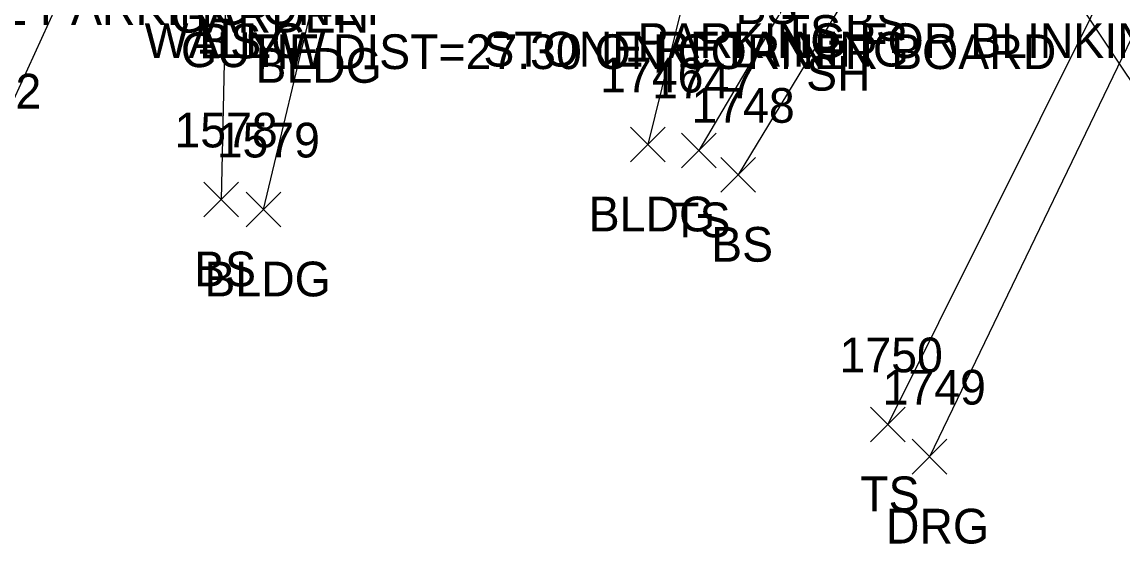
# Model space of a CAD drawing. Extents: x 1657482 to 1661439, y 647981 to 649041.
# Drawn here: x 1659845.2 to 1659908.5, y 648015.4 to 648045.5 of the extents above; entities that cross this region are included whole.
import ezdxf

# ---------------------------------------------------------------- set-up
doc = ezdxf.new("R2010")
doc.units = 0
for name, color, linetype in [('C_C', 7, 'Continuous'), ('DCP', 7, 'Continuous'), ('L_A', 7, 'Continuous'), ('L_C', 7, 'Continuous'), ('L_I', 7, 'Continuous'), ('L_TIC', 7, 'Continuous'), ('LBC', 7, 'Continuous'), ('LELB', 7, 'Continuous'), ('R_A', 7, 'Continuous'), ('R_I', 7, 'Continuous'), ('R_TIC', 7, 'Continuous'), ('RDG', 7, 'Continuous'), ('S_C', 7, 'Continuous'), ('U_A', 7, 'Continuous')]:
    doc.layers.add(name, color=color, linetype=linetype)

msp = doc.modelspace()

# ---------------------------------------------------------------- linework, layer by layer
at = {"layer": 'DCP'}
msp.add_lwpolyline([(1659891.836, 648067.894), (1659922.789, 648021.554)], dxfattribs=at)
at = {"layer": 'L_TIC'}
for points in [[(1659880.227, 648037.446), (1659882.227, 648039.446)], [(1659882.227, 648037.446), (1659880.227, 648039.446)], [(1659883.16, 648037.107), (1659885.16, 648039.107)], [(1659885.16, 648037.107), (1659883.16, 648039.107)], [(1659885.431, 648035.701), (1659887.431, 648037.701)], [(1659887.431, 648035.701), (1659885.431, 648037.701)], [(1659855.64, 648034.283), (1659857.64, 648036.283)], [(1659857.64, 648034.283), (1659855.64, 648036.283)], [(1659858.081, 648033.704), (1659860.081, 648035.704)], [(1659860.081, 648033.704), (1659858.081, 648035.704)], [(1659894.052, 648021.33), (1659896.052, 648023.33)], [(1659896.052, 648021.33), (1659894.052, 648023.33)]]:
    msp.add_lwpolyline(points, dxfattribs=at)
at = {"layer": 'LBC'}
msp.add_lwpolyline([(1659859.081, 648034.704), (1659862.022, 648047.005), (1659864.294, 648056.315), (1659866.191, 648055.955), (1659872.121, 648054.641), (1659883.804, 648052.077), (1659884.357, 648051.941), (1659884.475, 648051.61), (1659881.227, 648038.446)], dxfattribs=at)
at = {"layer": 'LELB'}
for points in [[(1659843.067, 648037.519), (1659849.136, 648050.781), (1659854.348, 648061.065), (1659857.118, 648074.796), (1659862.539, 648074.991), (1659866.841, 648074.821), (1659875.346, 648073.306), (1659881.621, 648071.832), (1659886.035, 648069.24), (1659889.385, 648068.66)], [(1659860.769, 648068.135), (1659861.322, 648064.402), (1659858.649, 648056.463), (1659856.936, 648048.408), (1659856.64, 648035.283)], [(1659913.188, 648060.644), (1659909.66, 648051.621), (1659895.052, 648022.33)], [(1659894.136, 648049.411), (1659886.431, 648036.701)], [(1659890.528, 648048.9), (1659884.16, 648038.107)]]:
    msp.add_lwpolyline(points, dxfattribs=at)
at = {"layer": 'R_TIC'}
for points in [[(1659896.454, 648019.47), (1659898.454, 648021.47)], [(1659898.454, 648019.47), (1659896.454, 648021.47)]]:
    msp.add_lwpolyline(points, dxfattribs=at)
at = {"layer": 'RDG'}
msp.add_lwpolyline([(1659913.188, 648060.644), (1659911.716, 648050.041), (1659897.454, 648020.47)], dxfattribs=at)

# ---------------------------------------------------------------- texts
at = {"layer": 'C_C'}
msp.add_text('TIE DIST=27.30 ON CORNER BOARD', height=2, dxfattribs=at).set_placement((1659858.167, 648042.795))
at = {"layer": 'L_A'}
for s, p in [('BS', (1659886.287, 648045.389)), ('GARDEN', (1659853.718, 648044.896)), ('BS', (1659892.577, 648044.411)), ('TS', (1659888.937, 648043.9)), ('WALLC', (1659852.231, 648043.43)), ('BS', (1659855.377, 648043.408)), ('BLDG', (1659858.613, 648042.005)), ('SH', (1659890.345, 648041.551)), ('BLDG', (1659877.817, 648033.446)), ('TS', (1659882.57, 648033.107)), ('BS', (1659884.872, 648031.701)), ('BS', (1659855.081, 648030.283)), ('BLDG', (1659855.672, 648029.704)), ('TS', (1659893.461, 648017.33))]:
    msp.add_text(s, height=2, dxfattribs=at).set_placement(p)
at = {"layer": 'L_C'}
msp.add_text('STONE RETAINING', height=2, dxfattribs=at).set_placement((1659871.751, 648042.941))
at = {"layer": 'L_I'}
for s, p in [('1746', (1659878.479, 648041.446)), ('1747', (1659881.468, 648041.107)), ('1562', (1659840.327, 648040.519)), ('1748', (1659883.738, 648039.701)), ('1578', (1659853.947, 648038.283)), ('1579', (1659856.381, 648037.704)), ('1750', (1659892.273, 648025.33))]:
    msp.add_text(s, height=2, dxfattribs=at).set_placement(p)
at = {"layer": 'R_A'}
msp.add_text('DRG', height=2, dxfattribs=at).set_placement((1659894.942, 648015.47))
at = {"layer": 'R_I'}
msp.add_text('1749', height=2, dxfattribs=at).set_placement((1659894.753, 648023.47))
at = {"layer": 'S_C'}
for s, p in [('TOWN HALL USE PARKING ONLY', (1659823.615, 648045.342)), ('PARKING FOR BLINKING LIGHT ONLY', (1659880.628, 648043.429))]:
    msp.add_text(s, height=2, dxfattribs=at).set_placement(p)
at = {"layer": 'U_A'}
msp.add_text('GUYW', height=2, dxfattribs=at).set_placement((1659854.321, 648042.905))

doc.saveas('drawing.dxf')
